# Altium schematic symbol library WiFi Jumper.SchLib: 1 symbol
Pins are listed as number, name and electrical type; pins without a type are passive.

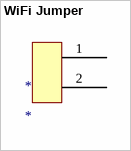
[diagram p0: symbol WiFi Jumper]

## WiFi Jumper
designator *
footprint WiFi Jumper
pins: 1, 2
